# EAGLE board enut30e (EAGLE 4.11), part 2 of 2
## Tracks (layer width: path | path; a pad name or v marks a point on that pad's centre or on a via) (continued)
P4  (via drill 0.2) (continued)
  Bottom 0.127: J5.51 25.3,73.76 25.3,71.6 24.5,70.8 24.5,39.5 v26.2,37.8
P5  (via drill 0.2)
  Top 0.127: IC3.102 40,67.2 38,69.2 33.4,69.2 31.9,70.7 24.8,70.7 24.15,71.35 24.15,72.37 J5.52 | IC1.56 32.3,36.5 31.43,37.38 26.77,37.38 26.4,37 v26,37
  Bottom 0.127: J5.52 24.2,72.32 24.2,38.8 v26,37
P6  (via drill 0.2)
  Top 0.127: IC1.57 32.3,36 31.3,37 27,37 26.2,36.2 v25.8,36.2 | IC3.103 39.5,67.2 37.8,68.9 33.2,68.9 31.7,70.4 24.05,70.4 22.9,71.55 22.9,74.3 22.27,74.93 J5.53
  Bottom 0.127: J5.53 22.9,73.62 22.9,70 23.9,69 23.9,38.6 25.4,37.1 25.4,36.6 v25.8,36.2
P7  (via drill 0.2)
  Top 0.127: IC1.58 32.2,35.5 31.07,36.62 27.23,36.62 26,35.4 v25.6,35.4 | J5.54 21.6,72 21.6,71.4 22.9,70.1 31.5,70.1 33,68.6 37.6,68.6 39,67.2 IC3.104
  Bottom 0.127: J5.54 21.59,70.91 23.6,68.9 23.6,38.4 25,37 25,36 v25.6,35.4
P8  (via drill 0.2)
  Top 0.127: IC1.59 32.2,35 30.95,36.25 28.75,36.25 28.2,35.7 v28.2,35.6 | J5.42 38.22,71 39.7,71 43.5,67.2 IC3.95
  Bottom 0.127: J5.42 35.04,70.6 31.6,70.6 27.6,66.6 27.6,40.4 28,40 28,35.8 v28.2,35.6
P9  (via drill 0.2)
  Top 0.127: IC1.60 32.2,34.5 30.82,35.88 29.38,35.88 28.35,34.85 v27.9,34.85 | J5.43 34.3,74.9 34.32,74.9 35.6,73.62 35.6,72.2 37.1,70.7 39.5,70.7 43,67.2 | 43,67.2 IC3.96 | 43,67.2
  Bottom 0.127: J5.43 35.3,73.92 35.3,71.75 34.45,70.9 31.5,70.9 27.3,66.7 27.3,40.3 27.7,39.9 27.7,35.05 v27.9,34.85
P10  (via drill 0.2)
  Top 0.127: IC2.100 56.4,6 55.7,6.7 50.9,6.7 49.3,8.3 v47.8,8.3 | IC1.63 34.2,33 34.5,33.3 34.5,36.8 34.9,37.2 35.45,37.2 36.05,36.6 v36.8,36.6
  Bottom 0.127: v47.8,8.3 47.8,10.1 44.3,13.6 44.3,29.5 37.2,36.6 v36.8,36.6
P11  (via drill 0.2)
  Top 0.127: IC1.64 31.88,32.5 30.57,31.2 28.3,31.2 v28,31.5
  Bottom 0.127: J5.45 33.1,73.58 33.1,72.2 32.1,71.2 31,71.2 30.5,70.7 29.5,70.7 27,68.2 27,40.2 27.4,39.8 27.4,32.1 v28,31.5
P12  (via drill 0.2)
  Top 0.127: J5.46 34.04,70.1 39.1,70.1 42,67.2 | IC1.66 32.6,31.5 31.8,30.7 v27.7,30.7 | 42,67.2 IC3.98 | 42,67.2
  Bottom 0.127: J5.46 30.35,71 29.4,71 26.7,68.3 26.7,40.1 27.1,39.7 27.1,31.3 v27.7,30.7
P13  (via drill 0.2)
  Top 0.127: J5.41 38.1,73.65 38.1,72.05 38.85,71.3 39.9,71.3 44,67.2 | IC1.67 32.6,31 31.65,30.05 v28.8,30.05 | 44,67.2 IC3.94 | 44,67.2
  Bottom 0.127: J5.41 38.05,73.71 38.05,71.6 36.75,70.3 31.7,70.3 27.9,66.5 27.9,40.5 28.3,40.1 28.3,36.2 28.8,35.7 v28.8,30.05
P14  (via drill 0.2)
  Top 0.127: v37.3,64.6 39.2,64.6 39.5,64.3 43.4,64.3 44.5,65.4 44.5,65.55 | IC1.68 34.2,30.5 34.5,30.8 34.5,32.6 35.2,33.3 v35.2,36.6 | J5.40 44.5,67.26 44.5,67.15 | 44.5,67.15 IC3.93 44.5,65.55 | 44.5,67.15 | 44.5,65.55 | 44.5,65.55
  Bottom 0.127: v37.3,64.6 37.3,63.2 37.9,62.6 37.9,48.5 36.8,47.4 34.6,47.4 33.4,46.2 33.4,37.6 34.4,36.6 v35.2,36.6
P15  (via drill 0.2)
  Top 0.127: J5.39 40.7,73.6 40.7,71.6 45,67.3 45,67.15 | IC1.69 34.2,30 34.8,30.6 34.8,32.4 35.8,33.4 v35.8,35.9 | v38.4,63.9 43.8,63.9 45,65.1 45,65.25 | 45,67.15 IC3.92 45,65.25 | 45,67.15 | 45,65.25
  Bottom 0.127: v35.8,35.9 35.8,36.9 35.3,37.4 34.2,37.4 33.7,37.9 33.7,46.1 34.7,47.1 36.9,47.1 38.2,48.4 38.2,63.7 v38.4,63.9
P16  (via drill 0.2)
  Top 0.127: v26.3,29.5 IC1.70 34.1,29.5 35.4,28.2 46.2,28.2 48.9,25.5 52.2,25.5 52.5,25.8 52.5,26.1 v53.2,26.8 | IC3.106 38,67.2 37.55,67.65 34.9,67.65 34.45,67.2 R10.2 34.45,67.7 34.15,68 31.6,68 31,67.4 29.5,67.4 29,66.9 24.2,66.9 19.05,72.05 J5.56 | IC5.12 58.23,29.12 v58.3,29.2 | v21.2,29.5 21.2,28.79 21.34,28.65 21.34,27.43 22.07,26.7 IC7.5 23.16,26.69 23.16,24.34 v23.3,24.2
  Bottom 0.127: J5.56 19.6,71.85 19.6,31.1 v21.2,29.5 v26.3,29.5 | JP5.1 32.4,7.2 29.7,9.9 29.7,17.8 v23.3,24.2 | v58.3,29.2 55.6,29.2 v53.2,26.8
P17  (via drill 0.2)
  Top 0.127: v26.9,29 IC1.71 34.2,29 35.3,27.9 46.1,27.9 48.8,25.2 52.55,25.2 53.1,25.75 v53.2,26 | J5.55 20.3,73.68 20.3,71.7 24.6,67.4 29,67.4 29.85,68.25 R11.2 30.25,68.25 30.3,68.3 37.4,68.3 38.5,67.2 IC3.105 | IC5.13 58.23,28.48 v58.3,28.4 | v21.82,29 21.82,28.39 22.25,27.96 IC7.6
  Bottom 0.127: v26.9,29 v21.82,29 20.9,29 19.3,30.6 19.3,65.5 17.95,66.85 17.95,73.83 J5.55 | v53.2,26 53.4,26 55.8,28.4 v58.3,28.4
P18  (via drill 0.2)
  Top 0.127: J5.62 11.43,70.77 14.6,67.6 20.2,67.6 25,62.8 33,62.8 34.3,61.5 34.95,61.5 | 34.95,61.5 | 34.95,61.5 IC3.115 | v27.5,28.5 IC1.72 | JP5.10 23.5,4.7 23.5,6.2 22.7,7 16.9,7 14.9,9 14.9,19.6 21.2,25.9 21.2,27 20.7,27.5 v20.7,28.5
  Bottom 0.127: J5.62 12.01,72.39 19,65.4 19,30.2 v20.7,28.5 v27.5,28.5
P19  (via drill 0.2)
  Top 0.127: J5.61 12.75,73.61 12.75,71.75 v12.3,71.3 12.3,70.95 15.35,67.9 20.4,67.9 25.2,63.1 33.1,63.1 33.7,62.5 34.9,62.5 | 34.9,62.5 | 34.9,62.5 IC3.113 | v29.7,28 IC1.73 | JP5.18 15.4,4.8 15.4,6.2 14.3,7.3 14.3,20.7 20,26.4 v20,28
  Bottom 0.127: v12.3,71.3 12.7,71.3 18.7,65.3 18.7,29.3 v20,28 v29.7,28
P20  (via drill 0.2)
  Top 0.127: J5.60 14.8,71.56 14.8,69.8 16.4,68.2 20.6,68.2 25.4,63.4 33.2,63.4 33.6,63 34.9,63 | 34.9,63 | 34.9,63 IC3.112 | v29.1,27.5 IC1.74
  Bottom 0.127: J5.60 13.16,72.39 12.1,73.45 10.8,73.45 10.15,72.8 10.15,72 11.55,70.6 12.6,70.6 14.3,68.9 14.3,31.7 18.5,27.5 v29.1,27.5
P21  (via drill 0.2)
  Top 0.127: J5.58 16.51,69.89 17.6,68.8 21,68.8 25.8,64 34.95,64 | 34.95,64 | 34.95,64 IC3.110 | v26.8,27 R15.2 IC1.75
  Bottom 0.127: J5.58 15.4,73.5 13,73.5 12.65,73.85 8.75,73.85 7.9,73 7.9,71.5 9.1,70.3 12.5,70.3 14,68.8 14,31.3 18.3,27 v26.8,27
P22  (via drill 0.2)
  Top 0.127: J5.57 17.8,73.64 17.8,71.8 20.5,69.1 21.2,69.1 24.5,65.8 34,65.8 34.2,66 35,66 35.8,65.2 37.3,65.2 37.5,65.4 37.5,66.2 | v29.6,25.7 31.6,25.7 32.1,25.2 35,25.2 IC1.76 | 37.5,66.2 | 37.5,66.2 IC3.107
  Bottom 0.127: J5.57 15.04,76.4 8,76.4 7.3,75.7 7.3,71.3 8.9,69.7 12.3,69.7 13.4,68.6 13.4,30.8 18.7,25.5 29.4,25.5 v29.6,25.7
P23  (via drill 0.2)
  Top 0.127: J5.59 15.3,73.6 15.3,70 16.8,68.5 20.8,68.5 25.6,63.7 33.3,63.7 33.5,63.5 IC3.111 | JP5.13 19.5,6.7 16.8,6.7 14.6,8.9 14.6,20.1 v20.6,26.2 | IC1.83 38.5,26.3 37.8,27 34.8,27 34.2,26.4 29.4,26.4 29.15,26.15 v26.8,26.15
  Bottom 0.127: J5.59 12.8,76.1 8.2,76.1 7.6,75.5 7.6,71.4 9,70 12.4,70 13.7,68.7 13.7,31 18.5,26.2 v20.6,26.2 26.75,26.2 v26.8,26.15
P24  (via drill 0.2)
  Top 0.127: v33.75,61 IC3.116 | v33.75,61 | v39,23.8 IC1.84 | IC2.14 65.35,3.15 63.4,1.2 52.6,1.2 46.4,7.4 v37.4,7.4 | v31.2,24.8 33,24.8 33.75,24.05 R14.2 33.75,22.25 36.5,19.5 v38.25,19.5
  Bottom 0.127: v39,23.8 39,22.3 38,21.3 38,19.75 v38.25,19.5 38.9,18.85 38.9,9.4 37.4,7.9 v37.4,7.4 | v33.75,61 34.9,59.85 34.9,55.1 32.1,52.3 29.4,52.3 28.8,51.7 28.8,41.2 29.5,40.5 29.5,36.2 29.7,36 29.7,31.02 31.2,29.52 v31.2,24.8
P25
  Top 0.127: 52.5,45.1 IC3.32 52.5,46.1 52.7,46.3 54.8,46.3 55.3,45.8 55.3,34.5 54.5,33.7 54.5,32.3 52.9,30.7 52.9,27.9 53.8,27 53.8,25.9 52.8,24.9 48.7,24.9 46,27.6 40.6,27.6 39.5,26.5 IC1.85
P26  (via drill 0.2)
  Top 0.127: IC1.99 46.5,24.6 47.3,23.8 v49.6,23.8 | v50.2,60 IC3.118 | v50.2,60
  Bottom 0.127: v49.6,23.8 49.4,24 49.4,31.4 54.7,36.7 54.7,42.3 51.4,45.6 51.4,58.8 v50.2,60
P27  (via drill 0.2)
  Top 0.127: J5.44 36.28,70.4 39.3,70.4 42.5,67.2 IC3.97 42.5,65.95 | v50.2,24.3 47.3,24.3 47,24.6 IC1.100 | 42.5,65.95 | v42.5,64.9 42.5,65.95
  Bottom 0.127: v42.5,64.9 47.2,64.9 51.7,60.4 51.7,45.8 55,42.5 55,36.6 49.7,31.3 49.7,30 50.5,29.2 50.5,24.6 v50.2,24.3
PLCLK1
  Top 0.127: IC3.30 51.5,46.2 51.9,46.6 54.9,46.6 55.6,45.9 55.6,36.8 58,34.4 R3.2
PLCLK2
  Top 0.127: IC3.38 55.35,47.5 55.1,47.25 55.1,46.9 55.9,46.1 55.9,36.9 57.4,35.4 60.3,35.4 61.55,34.15 R4.2
PNCS
  Top 0.127: J4.18 68.2,53 64.7,56.5 59.3,56.5 59.1,56.7 57.3,56.7 57.1,56.5 IC3.56
RCT
  Top 0.127: J1.6 81.56,16.8 80.37,15.6 C7.1
RD
  Top 0.127: IC6.7 79.19,59.85 79.2,59.85 79.2,59 77.7,57.5 77.7,56.1 77.2,55.6 77.2,53.1 78.7,51.6 RN1.2
RESET
  Top 0.127: IC10.3 R28.1
RI
  Top 0.127: R1.2 84.8,58.6 85.2,59 85.2,61.5 84.1,62.6 79.4,62.6 77.89,61.09 IC6.5
RTCX1
  Top 0.127: IC7.1 16.02,30.48 14.27,30.48 Y2.1
RTCX2
  Top 0.127: IC7.2 16.02,29.26 14.29,29.26 Y2.4
RTS
  Top 0.127: IC6.9 80.5,59.7 80.5,58.2 80.1,57.8 78.45,57.8 78,57.35 78,56 77.5,55.5 77.5,53.6 78.7,52.4 RN1.1
RXIC
  Top 0.127: R23.1 R22.1 77.25,6.25 78,5.5 C8.1
SHIELD  (via drill 0.2, 0.4)
  Top 0.127: CN1.1 85.1,50 85.3,50.2 v85.3,51.2 | CN1.4 85.1,52.4 85.3,52.2 v85.3,51.2 | CN1.3 84.9,51.6 v85.3,51.2 | CN1.2 84.9,50.8 v85.3,51.2 | CN2.5 85.1,54.3 85.3,54.5 v85.3,55.5 | CN2.8 85.1,56.7 85.3,56.5 85.3,55.55 | v85.3,55.5 85.3,55.55 | CN2.7 84.95,55.9 85.3,55.55 | CN2.6 84.9,55.1 v85.3,55.5
  Top 0.61: J6.CH2 2.45,68.04 v2.45,66.2 | J6.CH1 2.45,44.19 v2.45,46
  other vias: 3.81,76.07 5.52,75.37 6.22,73.66 5.52,71.95 3.81,71.25 2.1,71.95 1.4,73.66 2.1,75.37 3.81,6.22 5.52,5.52 6.22,3.81 5.52,2.1 3.81,1.4 2.1,2.1 1.4,3.81 2.1,5.52 93.98,76.07 95.69,75.37 96.39,73.66 95.69,71.95 93.98,71.25 92.27,71.95 91.57,73.66 92.27,75.37 93.98,6.22 95.69,5.52 96.39,3.81 95.69,2.1 93.98,1.4 92.27,2.1 91.57,3.81 92.27,5.52 1.5,63.5 1.5,60.5 1.5,57.5 1.5,54.5 1.5,51.5 1.5,48.5 1.5,21.5 1.5,18.5 1.5,15.5 1.5,12.5
  pour Ground (isolate 0.305): 0.64,77.47 6.99,77.47 6.99,42.55 2.54,42.55 2.54,7.62 12.06,7.62 12.06,1.91 83.82,1.91 83.82,13.97 80.64,13.97 80.64,36.2 86.36,36.2 86.36,48.9 83.19,48.9 83.19,57.15 89.53,57.15 89.53,60.33 86.36,60.33 86.36,68.58 90.17,68.58 90.17,77.47 97.16,77.47 97.16,0.64 0.64,0.64
  pour Top (isolate 0.203, no thermals): 3.81,6.67 arc-90 6.67,3.81 arc-90 3.81,0.95 arc-90 0.95,3.81 arc-90
  pour Top (isolate 0.203, no thermals): 93.98,6.67 arc-90 96.84,3.81 arc-90 93.98,0.95 arc-90 91.12,3.81 arc-90
  pour Top (isolate 0.203, no thermals): 3.81,76.52 arc-90 6.67,73.66 arc-90 3.81,70.8 arc-90 0.95,73.66 arc-90
  pour Top (isolate 0.203, no thermals): 93.98,76.52 arc-90 96.84,73.66 arc-90 93.98,70.8 arc-90 91.12,73.66 arc-90
TCK
  Top 0.127: JP5.7 JP5.8
  Bottom 0.127: JP5.7 25.5,6.7 18.7,6.7 J7.1
TD
  Top 0.127: IC6.10 81.14,59.8 81.15,59.8 81.15,58.37 80.28,57.5 78.65,57.5 78.3,57.15 78.3,55.9 77.8,55.4 77.8,54.8 78.3,54.3 RN2.4
TDI
  Top 0.127: J7.9 14,21.56 14,11.2 13.4,10.6 13.4,4.8 JP5.20 15.3,2.9 21.95,2.9 22.4,3.35 JP5.12
TDO
  Bottom 0.127: JP5.15 17.4,6.8 14.5,6.8 11.4,9.9 11.4,13.94 J7.3
TMS
  Top 0.127: JP5.3 JP5.4
  Bottom 0.127: JP5.3 30.4,6.6 30,7 18.8,7 14.8,11 14.8,16.8 13.82,17.78 J7.5
TPI+
  Top 0.127: IC2.29 73.5,7.5 74.75,6.25 R22.2 76.53,4.38 81.38,4.38 85.8,8.8 85.8,16.65 85.8,17.68 85.06,18.41 J1.7
TPI-
  Top 0.127: IC2.30 74.75,8 74.88,7.88 R23.2 74.9,8.28 75.38,8.75 77.38,8.75 77.88,8.25 83.25,8.25 85.4,10.4 85.4,16.4 84.73,17.07 83.52,17.07 81.56,19.02 J1.8
TPO+
  Top 0.127: IC2.33 73.38,9.5 73.78,9.1 R21.1 78.79,9.14 82.14,9.14 82.45,9.14 J1.1
TPO-
  Top 0.127: IC2.34 73.38,10 73.88,9.5 77.38,9.5 78.53,10.65 R20.1 78.77,10.67 80.17,10.67 J1.2
ULED
  Top 0.127: 38.5,45.45 | 38.5,45.45 IC3.4 | 38.5,45.45 38.5,46.8 38.3,47 37.4,47 35.7,45.3 31,45.3 30.3,44.6 15.8,44.6 13.75,42.55 IC15.1
VBAT
  Top 0.508: D3.C 24.75,29.2 | C1.+ 24.8,17.19 D3.C | 24.83,29.2 24.84,29.18 | D3.C 24.83,29.2 | IC7.7 24.79,29.23 24.83,29.2
VBOOST
  pour Top (isolate 0.127, no thermals): 77,42.9 76.2,42.9 75.9,42.6 75.9,40.2 78.4,40.2 78.4,41.1 79.2,41.1 79.2,42.9
VCC3  (via drill 0.2, 1)
  Top 0.127: R11.1 v31.4,66.55 32,67.15 R10.1 | RN4.5 30.1,49.6 30.3,49.4 30.9,49.4 | 30.9,49.4 31.7,49.4 | 31.7,49.4 32.5,49.4 | 30.9,49.4 RN4.6 | 31.7,49.4 RN4.7 | 32.5,49.4 RN4.8 | v40.4,19.4 39.6,19.4 RN6.6 | RN6.8 41.2,19.4 v40.4,19.4 | v40.4,19.4 RN6.7 | 59.5,37.2 59.5,36.3 59.9,35.9 61.9,35.9 62.5,36.5 62.5,38.35 62.95,38.8 63.45,38.8 63.48,38.83 IC9.5 | 32.5,49.4 32.7,49.2 v32.7,48.6 | IC11.5 8.95,34.35 8.6,34.7 7.05,34.7 5.35,36.4 R26.2 | R16.1 50.8,23.9 v50.2,23.3
  Top 0.254: RN3.8 59.4,68.8 v60.2,68.8 | RN3.7 v60.2,68.8 | RN3.6 61,68.8 v60.2,68.8 | RN5.6 RN5.7 RN5.8 v29.5,62 | v10.8,37.3 R25.2 | IC3.141 35,48.5 33.75,48.5 C38.1 v32.7,48.6 R27.2 | v40.5,42.67 40.5,43.48 C41.1 40.5,43.9 40.5,44.7 | 40.5,44.7 | 40.5,44.7 IC3.8 | IC5.14 56.23,27.82 C18.1 | v72.3,48.9 72.3,49.3 71.6,50 J4.24 | v70.2,62.1 70.65,62.1 71,61.75 J4.1 | IC9.4 59.1,38.83 59.1,37.6 59.5,37.2 C10.1 | IC3.42 57.45,49.5 C40.1 | IC5.2 64.2,27.18 64.2,25.4 63.5,25.4 63.5,25.45 C17.1 | IC3.84 49,68.2 C39.1 | IC13.5 56.05,24.55 56.4,24.9 56.4,26.1 v56,26.5
  Top 0.406: FB5.2 v62.35,44.9 | FB6.2 v84.35,66.9 | v52.1,3.8 FB3.2 | FB4.2 v56.6,22
  Top 0.508: C40.1 58.05,50 v59,50 | C17.1 v62.1,25.45 | R28.2 22.2,40.25 v22.2,41.1 | v49.88,68.45 49.85,68.45 49.75,68.35 C39.1 | v10.4,32.7 C49.1 10.35,33.7 IC11.5 | C48.1 15.15,38.3 IC15.5 | C48.1 15.3,38.25 IC10.5 | v15.2,37.4 C48.1 | IC12.5 15.05,33.7 15.1,33.75 C50.1 15.25,33.75 15.3,33.8 16.2,33.8 | 16.2,33.8 v16.25,33.8 | FB1.1 17.2,32.8 16.2,33.8 | R15.1 v28,24.2 | D3.A v24.8,32.2 | v56,26.5 C18.1 | v49.9,26.4 FB7.2
  Top 0.61: C10.1 59.45,37.2 v57.6,37.2 | v76.08,2.73 FB2.2 | J6.4 29.75,56.72 29.75,56.7 C5.1 29.75,57.2 v29.75,58
  Bottom 0.508: v52.1,3.8 54.3,1.6 72.2,1.6 73.33,2.73 v76.08,2.73
  other vias: 73.1,48.9
  pour Supply (isolate 0.254): 7.62,77.47 53.02,77.47 53.02,65.41 38.1,65.41 38.1,66.67 31.43,66.67 31.43,54.29 34.29,54.29 34.29,43.81 36.51,43.81 37.78,45.4 40.96,45.4 40.96,42.23 39.05,42.23 39.05,43.18 35.24,43.18 35.24,41.27 25.4,41.27 25.4,31.11 23.5,31.11 23.5,24.77 33.34,24.77 33.34,19.68 49.21,19.68 49.21,24.13 49.21,26.99 56.52,26.99 56.52,39.37 59.69,39.37 59.69,49.53 57.15,49.53 57.15,53.98 61.28,53.98 61.28,58.74 58.74,58.74 58.74,77.47 89.53,77.47 89.53,69.22 85.72,69.22 85.72,57.78 82.55,57.78 82.55,48.26 85.72,48.26 85.72,36.83 80.01,36.83 80.01,23.5 57.78,23.5 57.78,19.68 60.33,19.68 60.33,14.61 53.34,14.61 53.34,2.54 12.7,2.54 12.7,8.26 3.17,8.26 3.17,41.91 7.62,41.91
  pour Top (isolate 0.127, no thermals): 72,39.9 78.1,39.9 78.6,39.4 79.85,39.4 79.85,38.6 78.6,38.6 78.2,38.2 69.8,38.2 69.8,45.8 70.8,45.8 72,47 72,49.2 73.4,49.2 73.4,46.4 72,45
VCC3N  (via drill 0.2)
  Top 0.127: IC2.97 56,7.5 v56,7.25 56,7 IC2.98 | IC2.16 66.35,3 66.85,3 | IC2.17 66.85,3 | 66.85,3 67.1,3 v67.2,2.9 | R13.2 76.25,14.4 v75.45,13.6 | R12.2 v77.5,20.4 R7.2 R8.2
  Top 0.254: IC2.90 55.9,11 C19.1 55.55,10.65 v54.55,10.65 | C20.1 60.85,3.3 IC2.5 | C22.1 74.38,12 73.38,11 IC2.36 | C21.1 68.25,3 68.35,3.1 IC2.20 | IC2.73 59.85,21.25 60.05,21.25 | IC2.72 60.35,21.25 C25.1 | IC2.55 68.85,21 C23.1 | IC14.5 v77.2,17.8
  Top 0.406: v67.2,2.9 C21.1 | FB3.1 v57.8,3.8
  Top 0.508: C20.1 v59.4,2.9 | C25.1 60.05,21.25 60.05,21.55 v59.4,22.2 | C23.1 v68.75,22.1 | C22.1 74.85,12.45 74.85,12.9 75.45,13.5 v75.45,13.6
  pour Supply (isolate 0.254, no thermals): 69.22,2.54 53.98,2.54 53.98,13.97 60.96,13.97 60.96,20.32 58.42,20.32 58.42,22.86 80.01,22.86 80.01,13.97 76.2,13.97 76.2,12.06 69.22,12.06
VCCF  (via drill 0.2)
  Top 0.127: IC4.37 43.8,13.5 42.8,12.5 IC4.14
  Top 0.254: IC4.37 53.85,13.5 C16.1
  Top 0.406: FB4.1 52.4,20.9 v52.4,20
  Top 0.508: C16.1 55,13.75 v55.1,13.65
  Bottom 0.508: v55.1,13.65 52.4,16.35 v52.4,20
VCCIO  (via drill 0.2)
  Top 0.254: C47.1 36.8,43.7 37,43.9 IC3.1 | C44.1 55.02,67.83 54.5,67.3 IC3.73 | 33.6,55.5 C42.1 | IC3.127 33.6,55.5 | 33.6,55.5 | C46.1 57.9,47 IC3.37 | C43.1 33.4,64.85 33.75,64.5 IC3.109 | IC3.55 57.85,56 C45.1
  Top 0.406: FB5.1 v58,45.95
  Top 0.508: v56.2,68.17 56.2,68.2 55.83,67.83 C44.1 | C42.1 33.35,56.05 v32.9,56.5 | C47.1 v35.85,44.7 | v58,45.95 C46.1 | C43.1 33.45,64.95 33.45,65.1 34.3,65.1 v34.6,65.4 | C45.1 v59.05,55.85
  pour Supply (isolate 0.254): 32.07,66.04 37.47,66.04 37.47,64.77 53.66,64.77 53.66,77.47 58.1,77.47 58.1,58.1 60.64,58.1 60.64,54.61 56.52,54.61 56.52,48.9 59.05,48.9 59.05,44.77 55.88,44.77 55.88,46.04 37.47,46.04 36.2,44.45 34.92,44.45 34.92,54.93 32.07,54.93
VCCR
  Top 0.127: FB1.2 21.2,32.85 21.25,32.9 R2.2
  Top 0.508: C24.1 23.09,34.2 23.09,32.9 | 21.25,32.9 23.09,32.9 | IC7.8 23.09,30.5 23.09,32.9
VCCS
  Top 0.254: IC6.26 76.59,68.05 76.75,68.2 79.1,68.2 79.5,68.6 C51.1 79.55,69 79.95,69 80.4,68.55 80.75,68.55 FB6.1
VCORE  (via drill 0.2, 1)
  Top 0.254: IC1.94 44,24.2 v43.8,24 42.85,23.05 C29.1 | v46.5,39.35 IC1.27 46.5,41.7 C31.1 | IC9.1 59.1,40.77 59.1,41.9 59.5,42.3 C11.1 | C26.1 30.88,34 IC1.61
  Top 0.508: v30.62,35.1 30.6,35.1 30.6,34.27 C26.1
  Top 0.61: v57.6,42.4 C11.1
  pour Supply (isolate 0.254): 26.04,40.64 26.04,30.48 24.13,30.48 24.13,25.4 33.97,25.4 33.97,20.32 48.58,20.32 48.58,24.77 48.58,27.62 55.88,27.62 55.88,40.01 59.05,40.01 59.05,44.13 55.24,44.13 55.24,45.4 49.53,45.4 49.53,40.64 45.72,40.64 45.72,32.38 51.44,32.38 51.44,29.21 46.04,29.21 46.04,24.77 43.5,24.77 43.5,23.5 45.4,23.5 45.4,21.59 36.51,21.59 36.51,30.16 29.21,30.16 29.21,33.97 31.75,33.97 31.75,40.64
VDDIO  (via drill 0.2)
  Top 0.254: IC1.62 32.5,33.5 32,33 30.95,33 C34.1 | v43.8,22.55 44.65,22.55 44.9,22.8 C32.1 44.5,23.45 IC1.95 | C33.1 37.35,23.8 37.5,23.95 IC1.81 | C35.1 37.7,42.15 38,41.85 IC1.44 | C36.1 46.83,43.58 46.8,43.6 46,42.8 IC1.28 | C37.1 50.55,31.4 50.45,31.5 IC1.10
  Top 0.508: v30.27,31.75 30.25,31.75 30.25,32.3 C34.1 | C35.1 v36.75,42.2 | v47.88,43.62 47.85,43.65 46.92,43.65 C36.1 | v37.65,22.55 37.35,22.85 C33.1 | C37.1 50.6,30.75 v50.2,30.35 50.95,29.6 FB7.1
  pour Supply (isolate 0.254): 35.88,40.64 35.88,42.55 38.42,42.55 38.42,41.59 41.59,41.59 41.59,45.4 48.9,45.4 48.9,41.27 45.09,41.27 45.09,31.75 50.8,31.75 50.8,29.84 45.4,29.84 45.4,25.4 42.86,25.4 42.86,22.86 44.77,22.86 44.77,22.23 37.15,22.23 37.15,30.8 29.84,30.8 29.84,33.34 32.38,33.34 32.38,40.64
VSWITCH
  pour Top (isolate 0.127, no thermals): 73.6,45.8 78.3,45.8 79.1,45 79.1,43.5 78.8,43.2 76,43.2 75.6,42.8 75.6,40.2 73.6,40.2
WAKEUP  (via drill 0.2)
  Top 0.127: v53.3,32.7 53.1,32.9 53.1,36.8 53.65,37.35 | v55.4,17.8 55.4,17.5 56.4,16.5 IC2.79 | 53.65,37.35 R9.2 | v53.4,40.6 53.1,40.3 53.1,37.9 53.65,37.35 | v46,46.5 IC3.19 | v46,46.5
  Bottom 0.127: v55.4,17.8 55.4,19.2 52.3,22.3 52.3,29.95 53.6,31.25 53.6,32.4 v53.3,32.7 | v46,46.5 46,46 46.6,45.4 48,45.4 52.8,40.6 v53.4,40.6
XCTS
  Top 0.127: J3.8 90.16,54.7 87.1,54.7 86.2,53.8 83.75,53.8 83.4,54.15 83.4,54.9 83.2,55.1 CN2.3 RN2.6
XDCD
  Top 0.127: RN1.5 CN1.8 82.7,49.98 82.7,49.65 83.25,49.1 87.2,49.1 87.63,48.67 J3.1
XDSR
  Top 0.127: RN1.6 CN1.7 83.2,50.8 83.4,50.6 83.4,49.7 83.7,49.4 90,49.4 J3.6
XDTR
  Top 0.127: J3.4 86.62,56.08 85.5,57.2 83.7,57.2 83.4,56.9 83.4,56.1 83.2,55.9 CN2.2 RN2.7
XRD
  Top 0.127: RN1.7 CN1.6 83.2,51.6 83.4,51.8 83.4,52.6 83.7,52.9 85.95,52.9 87.63,51.22 J3.2
XRI
  Top 0.127: CN2.1 82.67,56.98 83.2,57.5 | J3.9 90.17,57.5 83.2,57.5 | R1.1 82.6,58.1 83.2,57.5
  Bottom 1.27: J3.9 R101.1
XRTS
  Top 0.127: RN1.8 CN1.5 82.67,52.77 83.1,53.2 86.2,53.2 87.4,52 90.14,52 J3.7
XTCK  (via drill 0.2)
  Top 0.127: v59.4,64.8 RN3.1 | JP5.9 25.3,6.7 27.5,6.7 30.2,9.4 30.2,19.4 30.9,20.1 35.4,20.1 36.6,18.9 41.2,18.9 41.3,19 48.2,19 v49.9,20.7 | IC3.67 | v54.2,62 IC3.67 | IC3.67 | IC3.67 v58.2,62
  Bottom 0.127: v58.2,62 59.4,63.2 v59.4,64.8 | v54.2,62 53.6,62 52,60.4 52,47.1 55.3,43.8 55.3,36.5 50.8,32 50.8,21.6 v49.9,20.7
XTD
  Top 0.127: J3.3 87.47,53.5 83.1,53.5 82.67,53.92 CN2.4 RN2.5
XTDI  (via drill 0.2)
  Top 0.127: 57.55,60 v58.6,60 | 57.55,60 IC3.63 53.65,60 | 57.55,60 | v61,64.8 RN3.3 | v40.7,17.2 43.4,17.2 44.6,18.4 49.8,18.4 51.4,20 v51.4,20.7 | v53.6,60 53.65,60 | 53.65,60
  Bottom 0.127: v40.7,17.2 40.7,7.9 35.4,2.6 21.6,2.6 JP5.14 | v53.6,60 52.6,59 52.6,47.3 55.9,44 55.9,36.3 51.4,31.8 v51.4,20.7 | v61,64.8 61,62.4 v58.6,60
XTDO  (via drill 0.2)
  Top 0.127: JP5.17 17.4,4.8 22.8,4.8 23.4,4.2 23.4,3.4 24,2.8 26.8,2.8 27.4,3.4 27.4,6.2 30.5,9.3 30.5,18.9 v31.1,19.5 | v33.8,58 IC3.122 | v33.8,58
  Bottom 0.127: v33.8,58 33.8,55.8 33.1,55.1 30.7,55.1 28.5,52.9 28.5,41 29.2,40.3 29.2,36.1 29.4,35.9 29.4,30.8 30.6,29.6 30.6,20 v31.1,19.5
XTMS  (via drill 0.2)
  Top 0.127: v60.2,64.8 RN3.2 | IC3.65 55.1,61 54.8,61.3 53.7,61.3 v53.6,61.2 | v50.6,20.2 49.1,18.7 41.8,18.7 41.45,18.35 v40.05,18.35 | IC3.65 | IC3.65 v58.2,61
  Bottom 0.127: v58.2,61 60.2,63 v60.2,64.8 | v40.05,18.35 39.8,18.1 39.8,7.8 35.8,3.8 JP5.2 | v53.6,61.2 52.3,59.9 52.3,47.2 55.6,43.9 55.6,36.4 51.1,31.9 51.1,21.3 50.6,20.8 v50.6,20.2

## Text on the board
Top: Ethernut
Bottom: 1 | 2 | R101 | ETHERNUT 3.0 REV-E | (C) EGNITE
tPlace: PORTS | ADDRESS | DATA | CONTROL | GND | PWR | It's alive! | It's alive! | SD/MMC | RS 232 | RESET | CPU | POWER | 5-24V | FLASH | ETHERNET | 100BaseT | ETHERNET | JTAG | www.egnite.de
Measures: 8.9 | 10.4 | grid 2.54 | 3.8 | 4.0 | 4.4 | 4.4 | 5.6 | 10.7 | 10.7 | 13.9 | grid 2.54 | 78.0 | 30.5 | grid 2.54 | 25.4 | 15.2 | 10.2 | 3.8 | 3.8 | d=3.0 | 3.8 | 19.1 | 4.0 | 98.0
